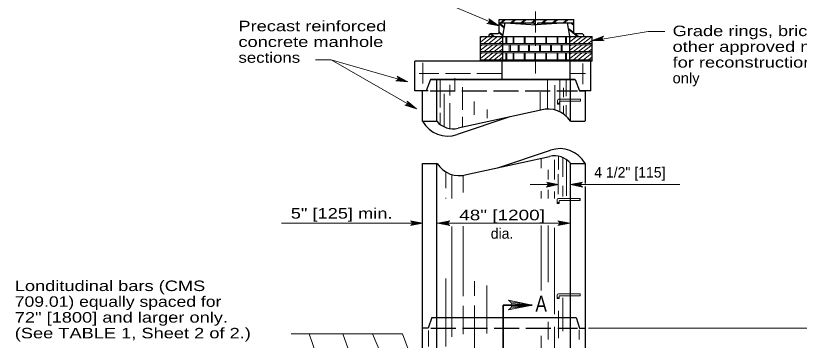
# Model space of a CAD drawing. Extents: x 1170.6 to 1204.6, y 975 to 1019.
# Drawn here: x 1186.32 to 1197.98, y 1005.96 to 1010.8 of the extents above; entities that cross this region are included whole.
import ezdxf
from ezdxf.enums import TextEntityAlignment as Align

# ---------------------------------------------------------------- set-up
doc = ezdxf.new("R2010")
doc.units = 0
doc.header["$LTSCALE"] = 0.062
for name, pattern in [('DOT_DASHED', [7.7, 5, -1.2, 0.3, -1.2]), ('LONG_DASHED', [7.5, 6, -1.5]), ('MEDIUM_DASHED', [4.5, 3, -1.5])]:
    doc.linetypes.add(name, pattern=pattern)
doc.layers.add('1', color=7, linetype='Continuous', lineweight=13)

msp = doc.modelspace()

# ---------------------------------------------------------------- linework, layer by layer
at = {"layer": '1'}
for p, q in [((1193.51125, 1010.6515), (1192.44667, 1011.10092)), ((1193.35542, 1010.68708), (1193.51125, 1010.64342)), ((1193.36483, 1010.69508), (1193.51125, 1010.64342)), ((1193.37092, 1010.70475), (1193.51125, 1010.64342)), ((1193.37267, 1010.73108), (1193.51125, 1010.64342)), ((1193.37408, 1010.71908), (1193.51125, 1010.64342)), ((1193.51542, 1010.68958), (1193.59508, 1010.62633)), ((1193.51542, 1010.67367), (1193.5925, 1010.61242)), ((1193.594, 1010.73742), (1193.53583, 1010.69142)), ((1193.61283, 1010.73667), (1193.556, 1010.69142)), ((1193.74725, 1010.73742), (1193.68908, 1010.69142)), ((1193.766, 1010.73667), (1193.70917, 1010.69142)), ((1193.90042, 1010.73742), (1193.84233, 1010.69142)), ((1193.91917, 1010.73667), (1193.86233, 1010.69142)), ((1194.05583, 1010.73742), (1193.99758, 1010.69133)), ((1194.07467, 1010.73667), (1194.01767, 1010.69133)), ((1194.21125, 1010.73742), (1194.15308, 1010.69133)), ((1194.23, 1010.73667), (1194.17317, 1010.69133)), ((1194.36725, 1010.73633), (1194.309, 1010.69017)), ((1194.38592, 1010.73542), (1194.32917, 1010.69017)), ((1194.52625, 1010.73742), (1194.46817, 1010.69142)), ((1194.54517, 1010.73667), (1194.48825, 1010.69142)), ((1194.57683, 1010.69075), (1194.62608, 1010.65175)), ((1194.59558, 1010.69117), (1194.62642, 1010.66658)), ((1193.37992, 1010.524), (1193.41825, 1010.49358)), ((1193.39383, 1010.52892), (1193.43942, 1010.49283)), ((1193.51333, 1010.54), (1193.57067, 1010.49425)), ((1193.516, 1010.55358), (1193.57358, 1010.508)), ((1194.54942, 1010.60658), (1194.62658, 1010.54517)), ((1194.55358, 1010.58783), (1194.6735, 1010.49275)), ((1194.64992, 1010.52675), (1194.69275, 1010.49275)), ((1194.90067, 1010.41967), (1195.73558, 1010.56133)), ((1195.73558, 1010.56133), (1195.98375, 1010.56133)), ((1193.34292, 1010.48517), (1193.24067, 1010.40383)), ((1193.26417, 1010.48517), (1193.24067, 1010.4665)), ((1193.4205, 1010.48575), (1193.29308, 1010.38442)), ((1193.49475, 1010.48633), (1193.36725, 1010.385)), ((1193.5695, 1010.48517), (1193.44208, 1010.38383)), ((1193.57133, 1010.42675), (1193.518, 1010.38442)), ((1193.61475, 1010.38317), (1193.61475, 1010.4845)), ((1193.62958, 1010.38317), (1193.62958, 1010.4845)), ((1193.72292, 1010.38317), (1193.72292, 1010.4845)), ((1193.73758, 1010.38317), (1193.73758, 1010.4845)), ((1193.888, 1010.38317), (1193.888, 1010.4845)), ((1193.90192, 1010.38317), (1193.90192, 1010.4845)), ((1194.04542, 1010.38317), (1194.04542, 1010.4845)), ((1194.05933, 1010.38317), (1194.05933, 1010.4845)), ((1194.209, 1010.38317), (1194.209, 1010.4845)), ((1194.22283, 1010.38317), (1194.22283, 1010.4845)), ((1194.37867, 1010.38317), (1194.37867, 1010.4845)), ((1194.39108, 1010.38317), (1194.39108, 1010.4845)), ((1194.50525, 1010.38317), (1194.50525, 1010.4845)), ((1194.51908, 1010.38317), (1194.51908, 1010.4845)), ((1194.67217, 1010.48608), (1194.57, 1010.40475)), ((1194.59342, 1010.48608), (1194.57, 1010.46742)), ((1194.74983, 1010.48667), (1194.62242, 1010.38533)), ((1194.824, 1010.48725), (1194.69658, 1010.38583)), ((1194.89883, 1010.48608), (1194.77142, 1010.38475)), ((1194.90067, 1010.42767), (1194.84733, 1010.38533)), ((1195.05533, 1010.47517), (1194.90067, 1010.42767)), ((1195.05167, 1010.46333), (1194.90067, 1010.42767)), ((1195.05192, 1010.45183), (1194.90067, 1010.42767)), ((1195.05692, 1010.43808), (1194.90067, 1010.42767)), ((1195.06467, 1010.42883), (1194.90067, 1010.42767)), ((1193.34292, 1010.36225), (1193.24067, 1010.28092)), ((1193.26417, 1010.36225), (1193.24067, 1010.34358)), ((1193.24075, 1010.38383), (1194.90275, 1010.38383)), ((1193.24075, 1010.36383), (1194.90275, 1010.36383)), ((1193.4205, 1010.36283), (1193.29308, 1010.26142)), ((1193.49475, 1010.36342), (1193.36725, 1010.262)), ((1193.5695, 1010.36225), (1193.44208, 1010.26083)), ((1193.57133, 1010.30383), (1193.518, 1010.26142)), ((1193.668, 1010.26133), (1193.668, 1010.36275)), ((1193.68433, 1010.26133), (1193.68433, 1010.36275)), ((1193.79933, 1010.26133), (1193.79933, 1010.36275)), ((1193.81625, 1010.26133), (1193.81625, 1010.36275)), ((1193.952, 1010.26133), (1193.952, 1010.36275)), ((1193.96675, 1010.26133), (1193.96675, 1010.36275)), ((1194.11642, 1010.26133), (1194.11642, 1010.36275)), ((1194.13025, 1010.26133), (1194.13025, 1010.36275)), ((1194.2815, 1010.26133), (1194.2815, 1010.36275)), ((1194.29542, 1010.26133), (1194.29542, 1010.36275)), ((1194.43883, 1010.26133), (1194.43883, 1010.36275)), ((1194.45433, 1010.26133), (1194.45433, 1010.36275)), ((1194.67208, 1010.36267), (1194.56992, 1010.28133)), ((1194.59342, 1010.36267), (1194.56992, 1010.344)), ((1194.74975, 1010.36325), (1194.62233, 1010.26183)), ((1194.82392, 1010.36383), (1194.6965, 1010.26242)), ((1194.89875, 1010.36267), (1194.77133, 1010.26125)), ((1194.90058, 1010.30425), (1194.84725, 1010.26183)), ((1193.34292, 1010.24058), (1193.24067, 1010.15933)), ((1193.26417, 1010.24058), (1193.24067, 1010.222)), ((1193.24075, 1010.26083), (1194.90275, 1010.26083)), ((1193.24075, 1010.24092), (1194.90275, 1010.24092)), ((1193.4205, 1010.24125), (1193.29308, 1010.13983)), ((1193.49475, 1010.24183), (1193.36725, 1010.14042)), ((1193.5695, 1010.24058), (1193.44208, 1010.13925)), ((1193.57133, 1010.18225), (1193.518, 1010.13983)), ((1193.61475, 1010.13858), (1193.61475, 1010.24)), ((1193.62958, 1010.13858), (1193.62958, 1010.24)), ((1193.72292, 1010.13858), (1193.72292, 1010.24)), ((1193.73758, 1010.13858), (1193.73758, 1010.24)), ((1193.888, 1010.13858), (1193.888, 1010.24)), ((1193.90192, 1010.13858), (1193.90192, 1010.24)), ((1194.04542, 1010.13858), (1194.04542, 1010.24)), ((1194.05933, 1010.13858), (1194.05933, 1010.24)), ((1194.209, 1010.13858), (1194.209, 1010.24)), ((1194.22283, 1010.13858), (1194.22283, 1010.24)), ((1194.37867, 1010.13858), (1194.37867, 1010.24)), ((1194.39108, 1010.13858), (1194.39108, 1010.24)), ((1194.50525, 1010.13858), (1194.50525, 1010.24)), ((1194.51908, 1010.13858), (1194.51908, 1010.24)), ((1194.67042, 1010.24033), (1194.56817, 1010.159)), ((1194.59167, 1010.24033), (1194.56817, 1010.22167)), ((1194.748, 1010.24092), (1194.62058, 1010.1395)), ((1194.82225, 1010.24142), (1194.69475, 1010.14008)), ((1194.897, 1010.24033), (1194.76958, 1010.13892)), ((1194.89883, 1010.18192), (1194.8455, 1010.1395)), ((1191.01758, 1010.14008), (1190.78483, 1010.14008)), ((1192.15825, 1009.80925), (1191.01758, 1010.14008)), ((1192.286, 1009.40758), (1191.01758, 1010.14008)), ((1193.24075, 1010.13925), (1194.90275, 1010.13925)), ((1193.24075, 1010.11925), (1194.90275, 1010.11925)), ((1191.99825, 1009.8335), (1192.15825, 1009.80925)), ((1192.00667, 1009.84258), (1192.15825, 1009.80925)), ((1192.00992, 1009.87933), (1192.15825, 1009.80925)), ((1192.01142, 1009.853), (1192.15825, 1009.80925)), ((1192.01283, 1009.86758), (1192.15825, 1009.80925)), ((1192.64067, 1009.427), (1192.64067, 1009.84558)), ((1192.85983, 1009.68867), (1192.85983, 1009.86417)), ((1194.23833, 1009.40567), (1194.23833, 1009.85617)), ((1194.41733, 1009.36692), (1194.41733, 1009.85617)), ((1194.51608, 1009.59708), (1194.51608, 1009.85617)), ((1192.78258, 1009.60683), (1192.78258, 1009.76708)), ((1192.974, 1009.39442), (1192.974, 1009.73433)), ((1194.34325, 1009.39417), (1194.34325, 1009.76383)), ((1194.476, 1009.58075), (1194.476, 1009.72133)), ((1192.69933, 1009.14192), (1192.69933, 1009.633)), ((1194.12717, 1009.38675), (1194.12717, 1009.65592)), ((1192.13558, 1009.46708), (1192.286, 1009.40758)), ((1192.14575, 1009.474), (1192.286, 1009.40758)), ((1192.15283, 1009.483), (1192.286, 1009.40758)), ((1192.15717, 1009.50908), (1192.286, 1009.40758)), ((1192.15742, 1009.497), (1192.286, 1009.40758)), ((1192.78258, 1009.11325), (1192.78258, 1009.49242)), ((1193.14683, 1009.31917), (1193.14683, 1009.51858)), ((1194.38358, 1009.4795), (1194.38358, 1009.53217)), ((1194.38358, 1009.4795), (1194.38358, 1009.53217)), ((1194.38358, 1009.49142), (1194.41558, 1009.49142)), ((1194.38358, 1009.49142), (1194.41558, 1009.49142)), ((1194.38358, 1009.4795), (1194.41558, 1009.4795)), ((1194.38358, 1009.4795), (1194.41558, 1009.4795)), ((1194.58408, 1009.55133), (1194.40367, 1009.55133)), ((1194.58408, 1009.55133), (1194.40367, 1009.55133)), ((1194.41575, 1009.4795), (1194.41575, 1009.51608)), ((1194.41575, 1009.4795), (1194.41575, 1009.51608)), ((1194.58408, 1009.52217), (1194.42183, 1009.52217)), ((1194.58408, 1009.52217), (1194.42183, 1009.52217)), ((1194.51608, 1009.29858), (1194.51608, 1009.46308)), ((1192.64067, 1009.19167), (1192.64067, 1009.35192)), ((1193.33817, 1009.27017), (1193.33817, 1009.39767)), ((1194.476, 1009.33175), (1194.476, 1009.4565)), ((1192.974, 1009.13483), (1192.974, 1009.28975)), ((1194.14083, 1008.52717), (1194.14083, 1008.67375)), ((1194.34217, 1008.35517), (1194.34217, 1008.65092)), ((1194.40058, 1008.50708), (1194.40058, 1008.70258)), ((1194.4655, 1008.39642), (1194.4655, 1008.68192)), ((1194.5175, 1008.11442), (1194.5175, 1008.65342)), ((1192.72317, 1008.22817), (1192.72317, 1008.47067)), ((1192.814, 1008.0755), (1192.814, 1008.43058)), ((1192.98283, 1008.16625), (1192.98283, 1008.42008)), ((1194.24475, 1008.35517), (1194.24475, 1008.503)), ((1194.39675, 1008.1375), (1194.39675, 1008.43733)), ((1194.2365, 1008.30358), (1194.39675, 1008.28117)), ((1194.73867, 1008.30358), (1194.57842, 1008.28117)), ((1193.97683, 1008.28117), (1194.39675, 1008.28117)), ((1194.14083, 1008.0755), (1194.14083, 1008.18325)), ((1194.23467, 1008.25642), (1194.39675, 1008.28117)), ((1194.24075, 1008.26683), (1194.39675, 1008.28117)), ((1194.24192, 1008.2925), (1194.39675, 1008.28117)), ((1194.24358, 1008.28117), (1194.39675, 1008.28117)), ((1194.24475, 1008.0755), (1194.24475, 1008.20383)), ((1194.34217, 1008.0755), (1194.34217, 1008.17975)), ((1194.4655, 1008.10408), (1194.4655, 1008.26233)), ((1194.73325, 1008.2925), (1194.57842, 1008.28117)), ((1194.57842, 1008.28117), (1196.20308, 1008.28117)), ((1194.73158, 1008.28117), (1194.57842, 1008.28117)), ((1194.73442, 1008.26683), (1194.57842, 1008.28117)), ((1194.7405, 1008.25642), (1194.57842, 1008.28117)), ((1192.72317, 1008.0755), (1192.72317, 1008.08375)), ((1194.5795, 1008.073), (1194.39908, 1008.073)), ((1194.5795, 1008.073), (1194.39908, 1008.073)), ((1194.37908, 1008.00117), (1194.37908, 1008.05383)), ((1194.37908, 1008.00117), (1194.37908, 1008.05383)), ((1194.37908, 1008.01308), (1194.411, 1008.01308)), ((1194.37908, 1008.01308), (1194.411, 1008.01308)), ((1194.37908, 1008.00117), (1194.411, 1008.00117)), ((1194.37908, 1008.00117), (1194.411, 1008.00117)), ((1194.41117, 1008.00117), (1194.41117, 1008.03775)), ((1194.41117, 1008.00117), (1194.41117, 1008.03775)), ((1194.5795, 1008.04383), (1194.41733, 1008.04383)), ((1194.5795, 1008.04383), (1194.41733, 1008.04383)), ((1192.21558, 1007.72925), (1192.37583, 1007.70683)), ((1192.221, 1007.71817), (1192.37583, 1007.70683)), ((1192.76392, 1007.72925), (1192.60375, 1007.70683)), ((1192.7585, 1007.71817), (1192.60375, 1007.70683)), ((1194.407, 1007.72925), (1194.56725, 1007.70683)), ((1194.41242, 1007.71817), (1194.56725, 1007.70683)), ((1190.27758, 1007.70683), (1192.37583, 1007.70683)), ((1192.21367, 1007.68208), (1192.37583, 1007.70683)), ((1192.21983, 1007.6925), (1192.37583, 1007.70683)), ((1192.22267, 1007.70683), (1192.37583, 1007.70683)), ((1192.59767, 1007.70683), (1194.56725, 1007.70683)), ((1192.75692, 1007.70683), (1192.60375, 1007.70683)), ((1192.75967, 1007.6925), (1192.60375, 1007.70683)), ((1192.76583, 1007.68208), (1192.60375, 1007.70683)), ((1192.814, 1006.01583), (1192.814, 1007.65725)), ((1192.98283, 1006.62108), (1192.98283, 1007.66417)), ((1194.14083, 1006.70683), (1194.14083, 1007.67425)), ((1194.24475, 1006.83058), (1194.24475, 1007.67425)), ((1194.34217, 1006.35258), (1194.34217, 1007.63983)), ((1194.40508, 1007.68208), (1194.56725, 1007.70683)), ((1194.41125, 1007.6925), (1194.56725, 1007.70683)), ((1194.41408, 1007.70683), (1194.56725, 1007.70683)), ((1192.72317, 1005.8715), (1192.72317, 1006.8825)), ((1193.15167, 1006.62792), (1193.15167, 1006.84483)), ((1193.3335, 1006.06408), (1193.3335, 1006.77933)), ((1194.37908, 1006.58467), (1194.37908, 1006.63733)), ((1194.37908, 1006.58467), (1194.37908, 1006.63733)), ((1194.37908, 1006.59658), (1194.411, 1006.59658)), ((1194.37908, 1006.59658), (1194.411, 1006.59658)), ((1194.37908, 1006.58467), (1194.411, 1006.58467)), ((1194.37908, 1006.58467), (1194.411, 1006.58467)), ((1194.5795, 1006.6565), (1194.39908, 1006.6565)), ((1194.5795, 1006.6565), (1194.39908, 1006.6565)), ((1194.41117, 1006.58467), (1194.41117, 1006.62125)), ((1194.41117, 1006.58467), (1194.41117, 1006.62125)), ((1194.5795, 1006.62733), (1194.41733, 1006.62733)), ((1194.5795, 1006.62733), (1194.41733, 1006.62733)), ((1194.4655, 1006.10142), (1194.4655, 1006.59675)), ((1192.98283, 1006.05717), (1192.98283, 1006.47667)), ((1193.15167, 1005.7995), (1193.15167, 1006.4835)), ((1193.68617, 1006.44), (1194.01042, 1006.48958)), ((1193.68992, 1006.53442), (1194.01042, 1006.48958)), ((1193.69842, 1006.46075), (1194.01042, 1006.48958)), ((1193.70083, 1006.51225), (1194.01042, 1006.48958)), ((1193.70408, 1006.48958), (1194.01042, 1006.48958)), ((1194.40058, 1005.99483), (1194.40058, 1006.40067)), ((1194.24475, 1005.97442), (1194.24475, 1006.23908)), ((1194.34217, 1005.69575), (1194.34217, 1006.16683)), ((1194.847, 1006.14658), (1198.57708, 1006.14658)), ((1192.07917, 1006.06167), (1190.42067, 1006.06167)), ((1191.01183, 1005.14358), (1190.68867, 1006.06167)), ((1191.44342, 1005.35658), (1191.19133, 1006.06167)), ((1191.88125, 1005.4725), (1191.63117, 1006.06167)), ((1192.29733, 1005.47317), (1192.07917, 1006.06167)), ((1194.14083, 1005.49308), (1194.14083, 1006.02958))]:
    msp.add_line(p, q, dxfattribs=at)
at = {"layer": '1', "linetype": 'DOT_DASHED'}
msp.add_line((1194.05933, 1009.93642), (1194.05933, 1010.90875), dxfattribs=at)
at = {"layer": '1', "lineweight": 25}
for p, q in [((1193.51542, 1010.54817), (1193.51542, 1010.73742)), ((1193.51542, 1010.73742), (1194.62683, 1010.73742)), ((1193.51542, 1010.69142), (1194.04217, 1010.69142)), ((1193.5705, 1010.4915), (1193.60692, 1010.69142)), ((1193.60692, 1010.69142), (1194.06892, 1010.65933)), ((1194.04217, 1010.66133), (1194.04217, 1010.69142)), ((1194.53067, 1010.69142), (1194.06808, 1010.65925)), ((1194.57025, 1010.4915), (1194.53417, 1010.68983)), ((1194.62642, 1010.54642), (1194.62642, 1010.73742)), ((1193.39825, 1010.52883), (1193.49308, 1010.52883)), ((1194.74358, 1010.52708), (1194.64875, 1010.52708)), ((1193.24075, 1010.48675), (1194.90275, 1010.48675)), ((1193.24075, 1010.11925), (1193.24075, 1010.48675)), ((1193.57067, 1010.11925), (1193.57067, 1010.48675)), ((1194.56808, 1010.11925), (1194.56808, 1010.48675)), ((1194.90275, 1010.11925), (1194.90275, 1010.48675)), ((1192.50758, 1010.11917), (1192.26475, 1010.11917)), ((1194.88275, 1010.11917), (1192.50758, 1010.11917)), ((1193.556, 1010.11533), (1193.556, 1009.84425)), ((1194.56808, 1010.11925), (1194.56808, 1010.02617)), ((1194.56808, 1010.02617), (1194.56808, 1009.84883)), ((1192.4955, 1009.84425), (1192.43075, 1009.6785)), ((1192.4955, 1009.84408), (1192.43075, 1009.6785)), ((1194.64625, 1009.84425), (1192.4955, 1009.84425)), ((1194.57783, 1009.22533), (1194.57783, 1009.85617)), ((1194.64625, 1009.84425), (1194.711, 1009.6785)), ((1192.43075, 1009.6785), (1192.26475, 1009.6785)), ((1192.37483, 1009.22533), (1192.37483, 1009.6785)), ((1192.46008, 1009.67933), (1192.3755, 1009.67933)), ((1194.711, 1009.6785), (1194.79658, 1009.6785)), ((1194.88275, 1009.6785), (1194.711, 1009.6785)), ((1194.79642, 1009.6785), (1194.79642, 1009.22533)), ((1194.13908, 1009.38933), (1192.9055, 1009.11992)), ((1193.67525, 1009.288), (1192.8905, 1009.02775)), ((1194.57783, 1009.22533), (1194.79092, 1009.22533)), ((1193.496, 1008.53292), (1194.28075, 1008.79317)), ((1193.03225, 1008.43158), (1194.26575, 1008.701)), ((1192.37483, 1008.59558), (1192.58792, 1008.59558)), ((1192.37483, 1008.08708), (1192.37483, 1008.59558)), ((1192.58792, 1007.73067), (1192.58792, 1008.59558)), ((1194.57783, 1008.59558), (1194.79092, 1008.59558)), ((1194.57783, 1007.76633), (1194.57783, 1008.59558)), ((1194.79642, 1008.59558), (1194.79642, 1008.29975)), ((1194.79642, 1008.25408), (1194.79642, 1007.77342)), ((1192.37483, 1005.80992), (1192.37483, 1008.08708)), ((1192.58792, 1005.25275), (1192.58792, 1007.78775)), ((1194.57783, 1003.56833), (1194.57783, 1007.78775)), ((1194.79642, 1007.78775), (1194.79642, 1004.34717)), ((1192.51692, 1006.30442), (1192.46292, 1006.14575)), ((1192.46308, 1006.1455), (1192.3785, 1006.1455)), ((1194.714, 1006.14467), (1194.7995, 1006.14467))]:
    msp.add_line(p, q, dxfattribs=at)
at = {"layer": '1', "linetype": 'LONG_DASHED'}
for p, q in [((1192.50758, 1009.93617), (1192.32633, 1009.93617)), ((1193.08958, 1009.93617), (1192.50758, 1009.93617)), ((1193.556, 1009.93617), (1193.10233, 1009.93617)), ((1194.80025, 1009.93617), (1194.56875, 1009.93617)), ((1192.46383, 1005.40008), (1192.46383, 1006.10867)), ((1194.70583, 1005.97467), (1194.70583, 1006.11975))]:
    msp.add_line(p, q, dxfattribs=at)
at = {"layer": '1', "linetype": 'LONG_DASHED', "lineweight": 25}
for p, q in [((1192.48908, 1009.67875), (1194.68, 1009.67875)), ((1192.50008, 1006.14492), (1194.683, 1006.14492))]:
    msp.add_line(p, q, dxfattribs=at)
at = {"layer": '1', "linetype": 'MEDIUM_DASHED'}
for p, q in [((1194.72567, 1009.55133), (1194.58725, 1009.55133)), ((1194.72567, 1009.55133), (1194.58725, 1009.55133)), ((1194.72567, 1009.52217), (1194.58725, 1009.52217)), ((1194.72567, 1009.52217), (1194.58725, 1009.52217)), ((1194.72567, 1009.52217), (1194.72567, 1009.55125)), ((1194.72567, 1009.52217), (1194.72567, 1009.55125)), ((1194.72108, 1008.073), (1194.58267, 1008.073)), ((1194.72108, 1008.073), (1194.58267, 1008.073)), ((1194.72108, 1008.04383), (1194.72108, 1008.07292)), ((1194.72108, 1008.04383), (1194.58267, 1008.04383)), ((1194.72108, 1008.04383), (1194.58267, 1008.04383)), ((1194.72108, 1006.6565), (1194.58267, 1006.6565)), ((1194.72108, 1006.6565), (1194.58267, 1006.6565)), ((1194.72108, 1006.62733), (1194.58267, 1006.62733)), ((1194.72108, 1006.62733), (1194.58267, 1006.62733)), ((1194.72108, 1006.62733), (1194.72108, 1006.65642)), ((1194.72108, 1006.62733), (1194.72108, 1006.65642))]:
    msp.add_line(p, q, dxfattribs=at)
at = {"layer": '1', "linetype": 'MEDIUM_DASHED', "lineweight": 25}
msp.add_line((1194.72108, 1008.04383), (1194.72108, 1008.07292), dxfattribs=at)
at = {"layer": '1', "lineweight": 35}
msp.add_line((1193.57775, 1006.48958), (1194.01042, 1006.48958), dxfattribs=at)
at = {"layer": '1'}
for points in [[(1193.36325, 1010.74675), (1193.51125, 1010.64342), (1193.33492, 1010.68192)], [(1195.08117, 1010.42067), (1194.90067, 1010.42767), (1195.06983, 1010.49058)], [(1191.99867, 1009.89375), (1192.15825, 1009.80925), (1191.9785, 1009.82583)], [(1192.14958, 1009.52558), (1192.286, 1009.40758), (1192.11458, 1009.464)], [(1194.21975, 1008.24583), (1194.39675, 1008.28117), (1194.21975, 1008.31658)], [(1194.75542, 1008.24583), (1194.57842, 1008.28117), (1194.75542, 1008.31658)], [(1192.19883, 1007.6715), (1192.37583, 1007.70683), (1192.19883, 1007.74225)], [(1192.78075, 1007.6715), (1192.60375, 1007.70683), (1192.78075, 1007.74225)], [(1194.39025, 1007.6715), (1194.56725, 1007.70683), (1194.39025, 1007.74225)], [(1193.65642, 1006.41875), (1194.01042, 1006.48958), (1193.65642, 1006.56033)]]:
    msp.add_lwpolyline(points, dxfattribs=at)
at = {"layer": '1', "lineweight": 25}
for points in [[(1194.094, 1010.66017), (1194.094, 1010.69142), (1194.62683, 1010.69142)], [(1192.26475, 1009.6785), (1192.26475, 1010.02617), (1192.26475, 1010.11917)], [(1194.88275, 1009.6785), (1194.88275, 1010.02617), (1194.88275, 1010.11917)], [(1192.37483, 1009.22533), (1192.58792, 1009.22533), (1192.58792, 1009.8405)], [(1192.49525, 1009.84425), (1194.64625, 1009.84425), (1194.711, 1009.6785)], [(1192.51692, 1006.30442), (1194.66358, 1006.30442), (1194.714, 1006.14467)]]:
    msp.add_lwpolyline(points, dxfattribs=at)
at = {"layer": '1', "linetype": 'LONG_DASHED'}
for points in [[(1192.37975, 1009.7865), (1192.37975, 1010.02617), (1192.37975, 1010.09433)], [(1194.76175, 1009.7785), (1194.76175, 1010.02617), (1194.76175, 1010.08625)]]:
    msp.add_lwpolyline(points, dxfattribs=at)
at = {"layer": '1', "lineweight": 35}
msp.add_lwpolyline([(1193.57775, 1006.48958), (1193.57775, 1005.58875), (1193.57775, 1003.83592)], dxfattribs=at)
at = {"layer": '1'}
for centre, radius, start, end in [((1193.33596, 1010.72002), 0.0382, 268.45926, 44.28539), ((1195.08953, 1010.45791), 0.0382, 121.17218, 256.99831), ((1191.97487, 1009.86377), 0.0382, 275.50882, 51.33495), ((1192.1196, 1009.50178), 0.0382, 262.54535, 38.37148), ((1194.20547, 1008.28124), 0.0382, 292.08605, 67.91218), ((1194.7697, 1008.28124), 0.0382, 112.08782, 247.91395), ((1192.18452, 1007.7069), 0.0382, 292.08605, 67.91218), ((1192.79501, 1007.7069), 0.0382, 112.08782, 247.91395), ((1194.37594, 1007.7069), 0.0382, 292.08605, 67.91218), ((1193.62784, 1006.48964), 0.0764, 292.08605, 67.91218)]:
    msp.add_arc(centre, radius, start, end, dxfattribs=at)
at = {"layer": '1', "lineweight": 25}
for centre, major_axis, start_param, end_param in [((1193.39663, 1010.49296), (0, 0.03579), 6.23518017, 7.85629289), ((1193.49553, 1010.54956), (0, -0.02102), 6.1570556, 7.79212712), ((1194.64621, 1010.54776), (0, -0.02102), 4.7742435, 6.40931502), ((1194.74511, 1010.49116), (0, 0.03579), 4.72196987, 6.33119044), ((1194.2498, 1008.98139), (0, 0.42442), 5.32468815, 6.56301094), ((1192.75192, 1009.47539), (0, -0.47104), 5.27203036, 6.60009478), ((1192.83472, 1009.46974), (0, -0.3578), 5.46438227, 6.49399063), ((1194.41934, 1008.34553), (0, 0.47104), 5.27203036, 6.60009478), ((1194.33654, 1008.35119), (0, 0.3578), 5.46438227, 6.49399063), ((1192.92146, 1008.83954), (0, -0.42442), 5.32468815, 6.56301094)]:
    msp.add_ellipse(centre, major_axis=major_axis, ratio=0.944544, start_param=start_param, end_param=end_param, dxfattribs=at)
at = {"layer": '1'}
for centre, major_axis, start_param, end_param in [((1194.40416, 1009.52941), (0, 0.02191), 0.02303975, 1.4456919), ((1194.40416, 1009.52941), (0, 0.02191), 0.02303975, 1.4456919), ((1194.4215, 1009.51605), (0, 0.00612), 6.2212346, 7.84973137), ((1194.4215, 1009.51605), (0, 0.00612), 6.2212346, 7.84973137), ((1194.3996, 1008.0511), (0, 0.02191), 0.02303975, 1.4456919), ((1194.3996, 1008.0511), (0, 0.02191), 0.02303975, 1.4456919), ((1194.41693, 1008.03773), (0, 0.00612), 6.2212346, 7.84973137), ((1194.41693, 1008.03773), (0, 0.00612), 6.2212346, 7.84973137), ((1194.3996, 1006.63458), (0, 0.02191), 0.02303975, 1.4456919), ((1194.3996, 1006.63458), (0, 0.02191), 0.02303975, 1.4456919), ((1194.41694, 1006.62121), (0, 0.00612), 6.2212346, 7.84973137), ((1194.41694, 1006.62121), (0, 0.00612), 6.2212346, 7.84973137)]:
    msp.add_ellipse(centre, major_axis=major_axis, ratio=0.944544, start_param=start_param, end_param=end_param, dxfattribs=at)

# ---------------------------------------------------------------- texts
for s, height, width, p in [('Precast reinforced', 0.156, 1.3, (1189.63817, 1010.56417)), ('Grade rings, bricks or', 0.156, 1.3, (1196.09692, 1010.49158)), ('concrete manhole', 0.156, 1.3, (1189.63817, 1010.3295)), ('other approved methods', 0.156, 1.3, (1196.09692, 1010.25758)), ('sections', 0.156, 1.2, (1189.63817, 1010.09483)), ('for reconstruction to grade ', 0.156, 1.3, (1196.09692, 1010.02358)), ('only', 0.156, 1.05, (1196.09692, 1009.78958)), ('Londitudinal bars (CMS', 0.156, 1.3, (1186.31108, 1006.69725)), ('709.01) equally spaced for', 0.156, 1.25, (1186.31108, 1006.46258)), ('A', 0.24, 0.8, (1194.05633, 1006.38875)), ('72" [1800] and larger only.', 0.156, 1.3, (1186.31108, 1006.22792)), ('(See TABLE 1, Sheet 2 of 2.)', 0.156, 1.3, (1186.31108, 1005.99325))]:
    msp.add_text(s, height=height, dxfattribs=dict(at, width=width)).set_placement(p)
msp.add_text('4 1/2" [115]', height=0.156, dxfattribs=at).set_placement((1194.93167, 1008.386))
for s, width, p in [('5" [125] min.', 1.3, (1191.17375, 1007.77583)), ('48" [1200]', 1.35, (1193.56042, 1007.7505))]:
    msp.add_text(s, height=0.156, dxfattribs=dict(at, width=width)).set_placement(p, align=Align.CENTER)
msp.add_text('dia.', height=0.156, dxfattribs=at).set_placement((1193.56046, 1007.4765), align=Align.CENTER)

doc.saveas('drawing.dxf')
